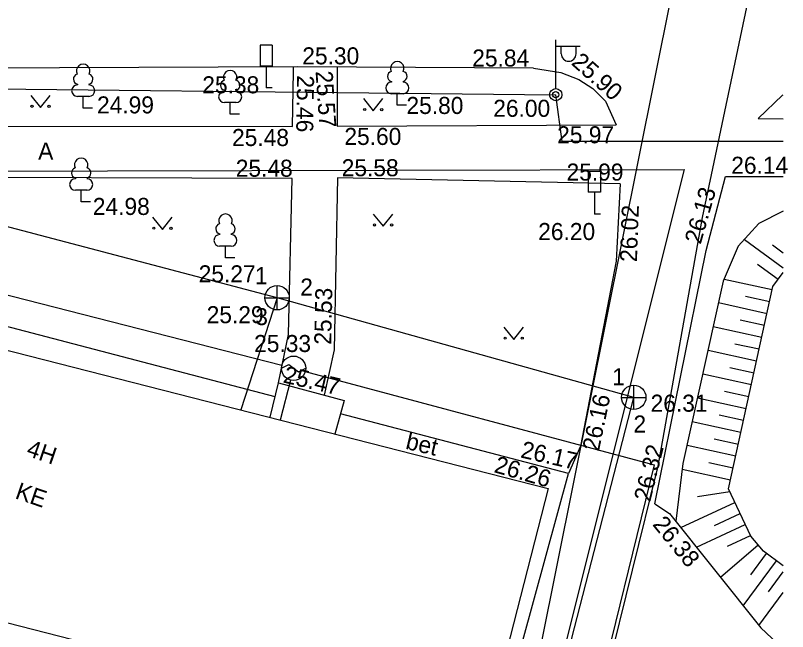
# Model space of a CAD drawing. Extents: x 714391 to 714584, y 6589993 to 6590151.
# Drawn here: x 714552.34 to 714584.1, y 6590068.08 to 6590093.39 of the extents above; entities that cross this region are included whole.
import ezdxf

# ---------------------------------------------------------------- set-up
doc = ezdxf.new("R2010")
doc.units = 0
for name, color, linetype in [('HALJASTUS', 7, 'Continuous'), ('HOONE', 7, 'Continuous'), ('HOONEDET', 7, 'Continuous'), ('KKAEV', 7, 'Continuous'), ('KORGUS', 7, 'Continuous'), ('KTRASS', 7, 'Continuous'), ('LIIKLUS', 7, 'Continuous'), ('MPKAABEL', 7, 'Continuous'), ('POST', 7, 'Continuous'), ('PUU', 7, 'Continuous'), ('RELJEEF', 7, 'Continuous'), ('SKTRASS', 7, 'Continuous'), ('TEE', 7, 'Continuous'), ('TORU NR', 7, 'Continuous'), ('VTRASS', 7, 'Continuous'), ('Слой 1', 7, 'Continuous')]:
    doc.layers.add(name, color=color, linetype=linetype)

msp = doc.modelspace()

# ---------------------------------------------------------------- linework, layer by layer
at = {"layer": 'HALJASTUS'}
for p, q in [((714552.97, 6590090.112), (714553.375, 6590089.607)), ((714553.375, 6590089.607), (714553.77, 6590090.112)), ((714566.652, 6590089.976), (714567.057, 6590089.471)), ((714567.057, 6590089.471), (714567.452, 6590089.976)), ((714557.982, 6590085.1), (714558.387, 6590084.595)), ((714558.387, 6590084.595), (714558.782, 6590085.1)), ((714567.058, 6590085.235), (714567.463, 6590084.73)), ((714567.463, 6590084.73), (714567.858, 6590085.235)), ((714572.431, 6590080.584), (714572.836, 6590080.079)), ((714572.836, 6590080.079), (714573.231, 6590080.584))]:
    msp.add_line(p, q, dxfattribs=at)
for centre, radius in [((714553.022, 6590089.662), 0.0428), ((714553.722, 6590089.662), 0.0452), ((714566.704, 6590089.527), 0.0428), ((714567.404, 6590089.527), 0.0452), ((714558.034, 6590084.65), 0.0428), ((714558.734, 6590084.65), 0.0452), ((714567.11, 6590084.785), 0.0428), ((714567.81, 6590084.785), 0.0452), ((714572.483, 6590080.135), 0.0428), ((714573.183, 6590080.135), 0.0452)]:
    msp.add_circle(centre, radius, dxfattribs=at)
at = {"layer": 'HOONE'}
for p, q in [((714544.792, 6590083.737), (714563.294, 6590079.021)), ((714563.279, 6590078.897), (714563.579, 6590079.047)), ((714563.579, 6590079.047), (714563.979, 6590078.747)), ((714563.979, 6590078.747), (714564.279, 6590078.897)), ((714563.655, 6590078.413), (714563.234, 6590076.767))]:
    msp.add_line(p, q, dxfattribs=at)
for points in [[(714571.553, 6590063.416), (714531.849, 6590073.579), (714534.607, 6590084.082)], [(714534.607, 6590084.082), (714574.255, 6590073.951), (714571.553, 6590063.416)], [(714564.262, 6590078.768), (714578.616, 6590074.926), (714573.649, 6590054.703), (714566.105, 6590024.628), (714563.31, 6590014.121), (714563.349, 6590014.272), (714562.951, 6590012.774), (714559.846, 6590001.436), (714579.323, 6589995.303), (714578.688, 6589992.711)], [(714562.82, 6590076.882), (714563.164, 6590078.293), (714565.864, 6590077.577), (714565.478, 6590076.194)]]:
    msp.add_lwpolyline(points, dxfattribs=at)
msp.add_circle((714563.779, 6590078.897), 0.5, dxfattribs=at)
at = {"layer": 'HOONEDET'}
msp.add_line((714563.164, 6590078.293), (714565.864, 6590077.577), dxfattribs=at)
at = {"layer": 'KKAEV'}
for p, q in [((714563.101, 6590081.294), (714563.101, 6590082.294)), ((714562.601, 6590081.794), (714563.601, 6590081.794)), ((714577.77, 6590077.201), (714577.77, 6590078.201)), ((714577.27, 6590077.701), (714578.27, 6590077.701))]:
    msp.add_line(p, q, dxfattribs=at)
for centre in [(714563.101, 6590081.794), (714577.77, 6590077.701)]:
    msp.add_circle(centre, 0.5, dxfattribs=at)
at = {"layer": 'KTRASS'}
for p, q in [((714563.101, 6590081.794), (714543.798, 6590086.868)), ((714563.101, 6590081.794), (714561.611, 6590077.182)), ((714577.77, 6590077.701), (714563.101, 6590081.794)), ((714571.457, 6590053.19), (714577.77, 6590077.701))]:
    msp.add_line(p, q, dxfattribs=at)
at = {"layer": 'LIIKLUS'}
for p, q in [((714562.401, 6590092.167), (714562.401, 6590091.317)), ((714562.901, 6590092.167), (714562.401, 6590092.167)), ((714562.901, 6590092.167), (714562.901, 6590091.317)), ((714562.901, 6590091.317), (714562.401, 6590091.317)), ((714562.651, 6590091.317), (714562.651, 6590090.417)), ((714562.901, 6590090.417), (714562.651, 6590090.417)), ((714575.9, 6590086.984), (714575.9, 6590086.134)), ((714576.4, 6590086.984), (714575.9, 6590086.984)), ((714576.4, 6590086.984), (714576.4, 6590086.134)), ((714576.4, 6590086.134), (714575.9, 6590086.134)), ((714576.15, 6590086.134), (714576.15, 6590085.234)), ((714576.4, 6590085.234), (714576.15, 6590085.234))]:
    msp.add_line(p, q, dxfattribs=at)
at = {"layer": 'MPKAABEL'}
msp.add_lwpolyline([(714460.809, 6590089.818), (714516.791, 6590090.163), (714543.78, 6590090.458), (714574.561, 6590090.139)], dxfattribs=at)
at = {"layer": 'POST'}
for p, q in [((714574.561, 6590090.389), (714574.561, 6590092.389)), ((714574.561, 6590092.139), (714575.561, 6590092.139)), ((714574.788, 6590091.818), (714574.788, 6590092.139)), ((714575.4, 6590091.818), (714575.4, 6590092.139)), ((714574.561, 6590090.139), (714574.561, 6590090.139))]:
    msp.add_line(p, q, dxfattribs=at)
for radius in [0.25, 0.127]:
    msp.add_circle((714574.561, 6590090.139), radius, dxfattribs=at)
msp.add_arc((714575.094, 6590091.818), 0.306, 180, 0, dxfattribs=at)
at = {"layer": 'PUU'}
for p, q in [((714554.886, 6590090.571), (714554.886, 6590090.541)), ((714555.366, 6590090.571), (714555.366, 6590090.541)), ((714567.804, 6590090.683), (714567.804, 6590090.653)), ((714568.284, 6590090.683), (714568.284, 6590090.653)), ((714560.933, 6590090.317), (714560.933, 6590090.287)), ((714561.413, 6590090.317), (714561.413, 6590090.287)), ((714568.284, 6590090.178), (714567.804, 6590090.178)), ((714568.044, 6590089.703), (714568.044, 6590090.178)), ((714555.366, 6590090.066), (714554.886, 6590090.066)), ((714555.126, 6590089.591), (714555.126, 6590090.066)), ((714561.413, 6590089.812), (714560.933, 6590089.812)), ((714561.173, 6590089.337), (714561.173, 6590089.812)), ((714555.506, 6590089.591), (714555.126, 6590089.591)), ((714568.424, 6590089.703), (714568.044, 6590089.703)), ((714561.553, 6590089.337), (714561.173, 6590089.337)), ((714554.804, 6590086.714), (714554.804, 6590086.684)), ((714555.284, 6590086.714), (714555.284, 6590086.684)), ((714555.284, 6590086.209), (714554.804, 6590086.209)), ((714555.044, 6590085.734), (714555.044, 6590086.209)), ((714555.424, 6590085.734), (714555.044, 6590085.734)), ((714560.738, 6590084.419), (714560.738, 6590084.389)), ((714561.218, 6590084.419), (714561.218, 6590084.389)), ((714561.218, 6590083.914), (714560.738, 6590083.914)), ((714560.978, 6590083.439), (714560.978, 6590083.914)), ((714561.358, 6590083.439), (714560.978, 6590083.439))]:
    msp.add_line(p, q, dxfattribs=at)
for centre, radius, start, end in [((714555.126, 6590091.111), 0.277, 332.5799, 207.4201), ((714568.044, 6590091.223), 0.277, 332.5799, 207.4201), ((714561.173, 6590090.857), 0.277, 332.5799, 207.4201), ((714567.854, 6590090.891), 0.212, 105.2441, 257.079), ((714568.234, 6590090.891), 0.212, 282.921, 74.7559), ((714554.936, 6590090.779), 0.212, 105.2441, 257.079), ((714555.316, 6590090.779), 0.212, 282.921, 74.7559), ((714560.983, 6590090.525), 0.212, 105.2441, 257.079), ((714561.363, 6590090.525), 0.212, 282.921, 74.7559), ((714554.889, 6590090.304), 0.237, 90, 270), ((714555.363, 6590090.304), 0.237, 270, 90), ((714567.806, 6590090.416), 0.237, 90, 270), ((714568.281, 6590090.416), 0.237, 270, 90), ((714560.935, 6590090.05), 0.237, 90, 270), ((714561.41, 6590090.05), 0.237, 270, 90), ((714555.044, 6590087.254), 0.277, 332.5799, 207.4201), ((714554.854, 6590086.922), 0.212, 105.2441, 257.079), ((714555.234, 6590086.922), 0.212, 282.921, 74.7559), ((714554.806, 6590086.446), 0.237, 90, 270), ((714555.281, 6590086.446), 0.237, 270, 90), ((714560.978, 6590084.959), 0.277, 332.5799, 207.4201), ((714560.788, 6590084.627), 0.212, 105.2441, 257.079), ((714561.168, 6590084.627), 0.212, 282.921, 74.7559), ((714560.74, 6590084.151), 0.237, 90, 270), ((714561.215, 6590084.151), 0.237, 270, 90)]:
    msp.add_arc(centre, radius, start, end, dxfattribs=at)
at = {"layer": 'RELJEEF'}
for p, q in [((714582.32, 6590084.192), (714583.92, 6590083.023)), ((714583.482, 6590083.963), (714583.92, 6590083.643)), ((714582.865, 6590083.175), (714583.714, 6590082.555)), ((714581.488, 6590082.564), (714583.467, 6590082.13)), ((714582.361, 6590081.861), (714583.36, 6590081.641)), ((714581.255, 6590081.592), (714583.252, 6590081.153)), ((714582.146, 6590080.884), (714583.145, 6590080.664)), ((714581.04, 6590080.615), (714583.038, 6590080.176)), ((714580.824, 6590079.639), (714582.823, 6590079.199)), ((714581.931, 6590079.907), (714582.931, 6590079.688)), ((714580.609, 6590078.662), (714582.609, 6590078.223)), ((714581.716, 6590078.931), (714582.716, 6590078.711)), ((714581.501, 6590077.954), (714582.501, 6590077.734)), ((714580.393, 6590077.686), (714582.394, 6590077.246)), ((714581.286, 6590076.977), (714582.287, 6590076.758)), ((714580.177, 6590076.709), (714582.18, 6590076.269)), ((714581.071, 6590076.001), (714582.072, 6590075.781)), ((714579.962, 6590075.733), (714581.965, 6590075.293)), ((714580.856, 6590075.024), (714581.858, 6590074.804)), ((714579.767, 6590074.752), (714581.75, 6590074.316)), ((714580.388, 6590073.625), (714581.72, 6590073.836)), ((714579.711, 6590072.346), (714581.931, 6590073.383)), ((714581.087, 6590072.437), (714582.143, 6590072.93)), ((714580.353, 6590071.542), (714582.355, 6590072.477)), ((714581.62, 6590071.582), (714582.566, 6590072.024)), ((714581.332, 6590070.315), (714582.882, 6590071.638)), ((714582.591, 6590070.413), (714583.233, 6590071.285)), ((714582.273, 6590069.136), (714583.635, 6590070.989)), ((714583.317, 6590069.712), (714583.92, 6590070.533)), ((714582.919, 6590068.326), (714583.92, 6590069.688))]:
    msp.add_line(p, q, dxfattribs=at)
for points in [[(714583.92, 6590085.347), (714582.914, 6590084.841), (714582.066, 6590083.914), (714581.45, 6590082.475), (714579.795, 6590074.976), (714579.502, 6590072.608)], [(714583.92, 6590070.78), (714583.101, 6590071.382), (714582.582, 6590071.99), (714581.669, 6590073.945), (714583.494, 6590082.253), (714583.92, 6590082.837)]]:
    msp.add_lwpolyline(points, dxfattribs=at)
at = {"layer": 'SKTRASS'}
msp.add_line((714573.957, 6590067.525), (714579.488, 6590095.048), dxfattribs=at)
at = {"layer": 'TEE'}
msp.add_line((714582.893, 6590089.16), (714583.92, 6590089.15), dxfattribs=at)
for points in [[(714573.651, 6590091.235), (714563.941, 6590091.279), (714547.616, 6590091.212), (714515.821, 6590091.083), (714495.803, 6590091.003), (714475.803, 6590090.885), (714460.229, 6590090.83)], [(714546.556, 6590088.84), (714546.656, 6590088.84), (714563.739, 6590088.838), (714563.771, 6590091.085), (714563.774, 6590091.278)], [(714565.573, 6590091.272), (714565.573, 6590091.091), (714565.573, 6590088.844), (714577.042, 6590088.905)], [(714573.651, 6590091.235), (714574.77, 6590091.052), (714575.514, 6590090.761), (714576.09, 6590090.387), (714576.614, 6590089.874), (714577.042, 6590088.905)], [(714583.92, 6590088.218), (714574.828, 6590088.218), (714574.561, 6590090.139)], [(714582.893, 6590089.16), (714583.888, 6590090.114), (714583.92, 6590090.135)], [(714563.164, 6590078.293), (714563.571, 6590080.29), (714563.722, 6590086.695), (714547.192, 6590086.755), (714546.8, 6590084.063)], [(714577.215, 6590086.481), (714565.584, 6590086.726), (714565.452, 6590079.655), (714565.032, 6590077.787)], [(714578.632, 6590073.323), (714580.749, 6590083.732), (714581.539, 6590086.783), (714583.92, 6590086.778)], [(714577.215, 6590086.481), (714577.042, 6590083.301), (714575.573, 6590075.701), (714575.085, 6590074.574)], [(714563.025, 6590077.723), (714548.722, 6590081.458), (714546.283, 6590082.061)], [(714561.103, 6590065.296), (714571.762, 6590062.449), (714575.085, 6590074.574), (714565.709, 6590077.022)], [(714578.632, 6590073.323), (714579.245, 6590072.93), (714583.002, 6590068.223)], [(714583.002, 6590068.223), (714583.92, 6590067.36)]]:
    msp.add_lwpolyline(points, dxfattribs=at)
at = {"layer": 'VTRASS'}
msp.add_lwpolyline([(714583.92, 6590101.451), (714582.627, 6590094.792), (714580.583, 6590085.094), (714578.759, 6590074.872), (714576.646, 6590066.323), (714576.499, 6590065.948), (714576.768, 6590065.956), (714576.95, 6590065.889)], dxfattribs=at)
at = {"layer": 'Слой 1'}
msp.add_lwpolyline([(714579.84, 6590087.07), (714574.08, 6590064.07), (714572.19, 6590056.5), (714562.09, 6590059.36), (714527.28, 6590069.21), (714532.4, 6590086.95)], close=True, dxfattribs=at)

# ---------------------------------------------------------------- texts
at = {"layer": 'HOONE'}
for s, p in [('4H', (714552.752, 6590075.317)), ('KE', (714552.289, 6590073.563))]:
    msp.add_text(s, height=0.7, rotation=341.0277, dxfattribs=at).set_placement(p)
at = {"layer": 'HOONEDET'}
msp.add_text('bet', height=0.7, rotation=346.6797, dxfattribs=at).set_placement((714568.35, 6590075.594))
at = {"layer": 'KORGUS'}
for s, p in [('25.30', (714564.137, 6590091.385)), ('25.84', (714571.127, 6590091.296)), ('25.38', (714560.025, 6590090.195)), ('24.99', (714555.695, 6590089.369)), ('25.80', (714568.421, 6590089.346)), ('26.00', (714571.991, 6590089.229)), ('25.97', (714574.619, 6590088.142)), ('25.48', (714561.248, 6590088.029)), ('25.60', (714565.869, 6590088.073)), ('26.14', (714581.78, 6590086.889)), ('25.48', (714561.401, 6590086.767)), ('25.58', (714565.758, 6590086.787)), ('25.99', (714575.007, 6590086.609)), ('24.98', (714555.522, 6590085.196)), ('26.20', (714573.84, 6590084.166)), ('25.27', (714559.876, 6590082.427)), ('25.29', (714560.204, 6590080.748)), ('25.33', (714562.156, 6590079.564)), ('26.31', (714578.463, 6590077.112))]:
    msp.add_text(s, height=0.7, dxfattribs=at).set_placement(p)
for s, rotation, p in [('25.90', 318.2245, (714575.164, 6590091.408)), ('25.57', 273.9068, (714564.683, 6590091.096)), ('25.46', 269.1231, (714563.923, 6590090.939)), ('26.13', 74.0546, (714580.519, 6590083.962)), ('26.02', 87.912, (714577.898, 6590083.252)), ('25.53', 88.7811, (714565.326, 6590079.857)), ('25.47', 346.8327, (714563.317, 6590078.318)), ('26.16', 78.2153, (714576.334, 6590075.454)), ('26.17', 347.2109, (714573.082, 6590075.236)), ('26.32', 76.0683, (714578.444, 6590073.382)), ('26.26', 344.1047, (714571.988, 6590074.632)), ('26.38', 309.2072, (714578.515, 6590072.47))]:
    msp.add_text(s, height=0.7, rotation=rotation, dxfattribs=at).set_placement(p)
at = {"layer": 'TEE'}
msp.add_text('A', height=0.7, dxfattribs=at).set_placement((714553.274, 6590087.473))
at = {"layer": 'TORU NR'}
for s, p in [('1', (714562.184, 6590082.352)), ('2', (714564.054, 6590081.885)), ('3', (714562.205, 6590080.669)), ('1', (714576.882, 6590078.196)), ('2', (714577.757, 6590076.255))]:
    msp.add_text(s, height=0.7, dxfattribs=at).set_placement(p)

doc.saveas('drawing.dxf')
